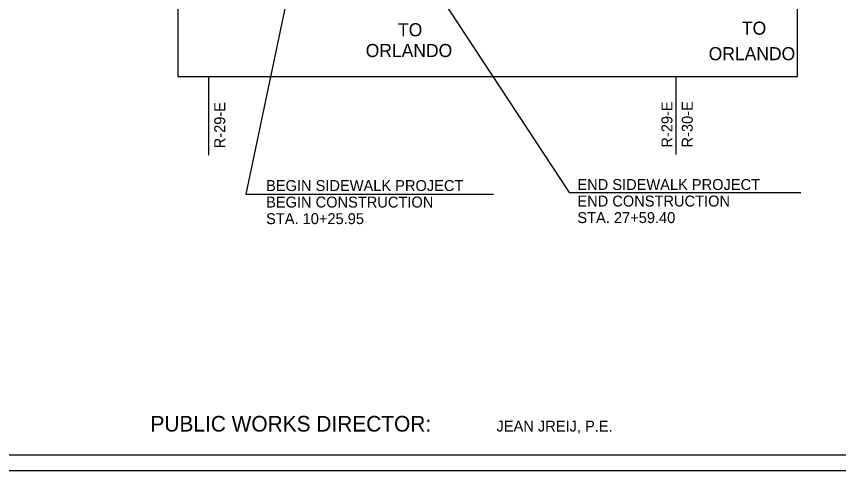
# Model space of a CAD drawing. Extents: x 2157516 to 2331756, y 2153820 to 2265756.
# Drawn here: x 2213121 to 2268726, y 2153820 to 2184545 of the extents above; entities that cross this region are included whole.
import ezdxf

# ---------------------------------------------------------------- set-up
doc = ezdxf.new("R2010")
doc.units = 0
for name, color, linetype in [('Default', 7, 'Continuous'), ('LeaderLine_dp', 7, 'Continuous'), ('MapOutline_dp', 7, 'Continuous'), ('PlotBorder_dp', 7, 'Continuous'), ('SheetBorder_dp', 7, 'Continuous'), ('TextLabel', 7, 'Continuous'), ('TextNotes', 7, 'Continuous')]:
    doc.layers.add(name, color=color, linetype=linetype)

msp = doc.modelspace()

# ---------------------------------------------------------------- linework, layer by layer
at = {"layer": 'LeaderLine_dp'}
for p, q in [((2233677, 2196432), (2228628, 2172526)), ((2235280, 2195821), (2250505, 2172636)), ((2228628, 2172526), (2245393, 2172526)), ((2250505, 2172636), (2266177, 2172636))]:
    msp.add_line(p, q, dxfattribs=at)
at = {"layer": 'MapOutline_dp'}
msp.add_lwpolyline([(2224044, 2180484), (2265958, 2180484), (2265958, 2222724), (2224044, 2222724)], close=True, dxfattribs=at)
at = {"layer": 'PlotBorder_dp'}
msp.add_lwpolyline([(2157516, 2153820), (2331756, 2153820), (2331756, 2265756), (2157516, 2265756)], close=True, dxfattribs=at)
at = {"layer": 'SheetBorder_dp'}
msp.add_line((2163324, 2154876), (2325948, 2154876), dxfattribs=at)
at = {"layer": 'TextNotes'}
for p, q in [((2226131, 2175148), (2226131, 2180428)), ((2257754, 2175204), (2257754, 2180484))]:
    msp.add_line(p, q, dxfattribs=at)

# ---------------------------------------------------------------- texts
at = {"layer": 'Default'}
for s, p in [('TO', (2262189, 2183310)), ('TO', (2238929, 2183203)), ('ORLANDO', (2236744, 2181798)), ('ORLANDO', (2259941, 2181584))]:
    msp.add_text(s, height=884.8, rotation=360, dxfattribs=at).set_placement(p)
at = {"layer": 'TextLabel'}
for s, p in [('BEGIN SIDEWALK PROJECT', (2230006, 2172733)), ('END SIDEWALK PROJECT', (2251061, 2172803)), ('BEGIN CONSTRUCTION', (2230006, 2171614)), ('END CONSTRUCTION', (2251061, 2171684)), ('STA. 10+25.95', (2230006, 2170494)), ('STA. 27+59.40', (2251061, 2170564))]:
    msp.add_text(s, height=739.2, dxfattribs=at).set_placement(p)
at = {"layer": 'TextNotes'}
for s, p in [('R-29-E', (2227240, 2175623)), ('R-29-E', (2257490, 2175668)), ('R-30-E', (2258863, 2175679))]:
    msp.add_text(s, height=739.2, rotation=90, dxfattribs=at).set_placement(p)
for s, height, p in [('PUBLIC WORKS DIRECTOR:', 1056, (2222185, 2156460)), ('       JEAN JREIJ, P.E.       ', 739.2, (2243669, 2156457))]:
    msp.add_text(s, height=height, dxfattribs=at).set_placement(p)

doc.saveas('drawing.dxf')
